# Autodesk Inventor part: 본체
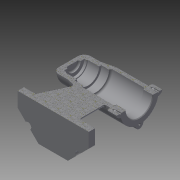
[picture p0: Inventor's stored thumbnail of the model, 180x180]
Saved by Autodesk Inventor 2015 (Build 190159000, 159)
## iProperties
Created: 2019-12
Part Number: 본체
Material: 일반
Document SubType Name: Modeling
Designer: CAD-08
Density: 1 g/cm^3
Appearance: 기본값
Author: CAD-08
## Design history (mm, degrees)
sketch "스케치1" dims "d0" = 112
  geometry: L1 (0, -56)-(-39.598, -39.598); L2 (-39.598, -39.598)-(-56, 0); L3 (-56, 0)-(-39.598, 39.598); L4 (-39.598, 39.598)-(0, 56); L5 (0, 56)-(39.598, 39.598); L6 (39.598, 39.598)-(56, 0); L7 (56, 0)-(39.598, -39.598); L8 (39.598, -39.598)-(0, -56); L9 (-23.196, -56)-(-56, -23.196); L10 (-56, -23.196)-(-56, 23.196); L11 (-56, 23.196)-(-23.196, 56); L12 (-23.196, 56)-(23.196, 56); L13 (23.196, 56)-(56, 23.196); L14 (56, 23.196)-(56, -23.196); L15 (56, -23.196)-(23.196, -56); L16 (23.196, -56)-(-23.196, -56); 4 further points
  constraints: 32 end point, 3 coincident, 1 horizontal alignment, 1 midpoint, 1 vertical alignment, 36 other
extrude "돌출1" new body sketch "스케치1" distance "d1" = 10; taper "d2" = 0 deg
sketch "스케치2"
  geometry: L1 (56, 23.196)-(23.196, 56) reference; L2 (-23.196, 56)-(-56, 23.196) reference; L3 (0, 0)-(-27.881, 0); L4 (-27.881, 0)-(0, 0); L5 (0, 30.128)-(0, 0); L6 (0, 0)-(-39.598, 39.598); C1 r 5 at (-39.598, 39.598); C2 r 5 at (39.598, 39.598); C3 r 5 at (-39.598, -39.598); C4 r 5 at (39.598, -39.598)
  constraints: 8 end point, 4 centre point, 2 midpoint, 2 symmetric about line, 1 collinear, 1 horizontal, 1 perpendicular, 2 other
  dimensions: "d3" = 10 diameter of C2; "d4" = 10 diameter of C1
extrude "돌출2" cut sketch "스케치2" distance "d5" = 10; taper "d6" = 0 deg
sketch "스케치3"
  geometry: L1 (56, -23.196)-(56, 23.196) reference; L2 (23.196, 56)-(-23.196, 56) reference; L3 (-56, 23.196)-(-56, -23.196) reference; L4 (-23.196, -56)-(23.196, -56) reference; L5 (-38, 4)-(31, 4); L6 (31, 4)-(31, -4); L7 (31, -4)-(-38, -4); L8 (-38, -4)-(-38, 4); L9 (4, -36)-(-4, -36); L10 (-4, -36)-(-4, 36); L11 (-4, 36)-(4, 36); L12 (4, 36)-(4, -36); 1 further point
  constraints: 16 end point, 4 parallel, 2 horizontal, 2 perpendicular
  dimensions: "d7" = 8 distance of L10.end L11.end; "d8" = 8 distance of L5.end L6.end; "d9" = 18 distance between parallel lines of L8 L3; "d10" = 25 distance between parallel lines of L1 L6; "d11" = 20 distance between parallel lines of L2 L11; "d12" = 20 distance between parallel lines of L4 L9; "d13" = 4 distance from line of point (0, 0) L10; "d14" = 4 distance from line of point (0, 0) L5
extrude "돌출3" join sketch "스케치3" distance "d15" = 70; taper "d16" = 0 deg
feature "면 기울기1" dims angle "d17" = 25 deg
feature "면 기울기2" dims angle "d18" = 20 deg
sketch "스케치4"
  geometry: L1 (56, 0)-(-56, 0) reference; L2 (-56, 0)-(-56, 10) reference; L3 (-56, 10)-(-38, 10) reference; L4 (-38, 10)-(-5.358, 80) reference; L5 (-5.358, 80)-(31, 80) reference; L6 (31, 80)-(31, 10) reference; L7 (31, 10)-(56, 10) reference; L8 (56, 10)-(56, 0) reference; L9 (-11, 110)-(56, 110); L10 (56, 110)-(56, 80); L11 (56, 80)-(-56, 80); L12 (-56, 80)-(-56, 105); L13 (-56, 105)-(-31, 105); L14 (-31, 105)-(-11, 110); 1 further point
  constraints: 12 end point, 2 collinear, 2 horizontal, 2 parallel, 1 perpendicular
  dimensions: "d20" = 112 distance between parallel lines of L10 L12; "d21" = 45 distance from line of L12 L9.start; "d22" = 25 distance of L12.end L13.end; "d23" = 30 distance between parallel lines of L11 L9; "d24" = 25 distance between parallel lines of L11 L13
revolve "회전1" sketch "스케치4" stored, may be unused: angle "d25" = 90 deg
sketch "스케치5"
  geometry: C1 r 30 at (0, 0) reference; 1 further point
hole "구멍1" sketch "스케치5" at (0, 0) diameter "d26" = 42; stored, may be unused: countersink angle "d30" = 90 deg, drill point angle "d32" = 0 deg; dims "d27" = 6, "d28" = 4, "d29" = 2, "d31" = 15
sketch "스케치6"
  geometry: C1 r 21 at (0, 0) reference; 1 further point
hole "구멍2" sketch "스케치6" at (0, 0) diameter "d33" = 48; stored, may be unused: countersink angle "d37" = 90 deg, drill point angle "d39" = 0 deg; dims "d34" = 6, "d35" = 4, "d36" = 2, "d38" = 54
sketch "스케치7"
  geometry: C1 r 24 at (0, 0) reference; 1 further point
hole "구멍3" sketch "스케치7" at (0, 0) diameter "d40" = 42; stored, may be unused: countersink angle "d44" = 90 deg, drill point angle "d46" = 0 deg; dims "d41" = 6, "d42" = 4, "d43" = 2, "d45" = 12
sketch "스케치8"
  geometry: C1 r 21 at (0, 0) reference; 1 further point
hole "구멍4" sketch "스케치8" at (0, 0) diameter "d47" = 35; stored, may be unused: countersink angle "d51" = 90 deg, drill point angle "d53" = 0 deg; dims "d48" = 6, "d49" = 4, "d50" = 2, "d52" = 18
sketch "스케치9"
  geometry: C1 r 17.5 at (0, 0) reference; 1 further point
hole "구멍5" sketch "스케치9" at (0, 0) diameter "d54" = 32; stored, may be unused: countersink angle "d58" = 90 deg, drill point angle "d60" = 0 deg; dims "d55" = 6, "d56" = 4, "d57" = 2, "d59" = 4
sketch "스케치10"
  geometry: C1 r 16 at (0, 0) reference; 1 further point
hole "구멍6" sketch "스케치10" at (0, 0) diameter "d61" = 21; stored, may be unused: countersink angle "d65" = 90 deg, drill point angle "d67" = 0 deg; dims "d62" = 6, "d63" = 4, "d64" = 2, "d66" = 3
sketch "스케치11"
  geometry: C1 r 21 at (0, 0) reference; C2 r 6 at (0, 30); 2 further points
  constraints: 2 vertical alignment, 1 centre point, 1 other
  dimensions: "d68" = 12 diameter of C2
extrude "돌출4" join sketch "스케치11" distance "d69" = 16; taper "d70" = 0 deg
sketch "스케치12"
  geometry: A1 r 6 centre (0, 0) between (5.97, -0.6) and (-5.97, -0.6) reference; 1 further point
hole "구멍7" sketch "스케치12" at (0, 0) diameter "d71" = 3.242; stored, may be unused: countersink angle "d75" = 90 deg, drill point angle "d77" = 118 deg; dims "d72" = 8, "d73" = 4, "d74" = 2, "d76" = 11
fillet "모깎기1" dims "d78" = 10
fillet "모깎기2" dims "d79" = 3
fillet "모깎기3" dims "d80" = 1
fillet "모깎기4" dims "d84" = 0.3
fillet "모깎기5" dims "d85" = 3
chamfer "모따기1" distance "d86" = 1; stored, may be unused: second distance "d87" = 2, angle "d88" = 45 deg
fillet "모깎기6" dims "d89" = 3
fillet "모깎기7" dims "d90" = 3
fillet "모깎기8" dims "d91" = 3
fillet "모깎기9" dims "d92" = 3
node "작업 평면1"
sketch "스케치13"
  geometry: L1 (33.5, 36)-(33.5, 30.171) reference; L2 (-33.131, 30)-(16.5, 30) reference; 2 further points
  constraints: 1 other
  dimensions: "d93" = 41 distance from line of L1 point (-7.5, 0); "d94" = 30 distance from line of L2 point (-7.5, 0)
feature "엠보싱1" sketch "스케치13" dims "d95" = 0.6, "d96" = 0
fillet "모깎기10" dims "d97" = 3
node "솔리드1"
pattern_circular "원형 패턴1" dims "d82" = 360 deg
node "절단 모서리 투영1"
